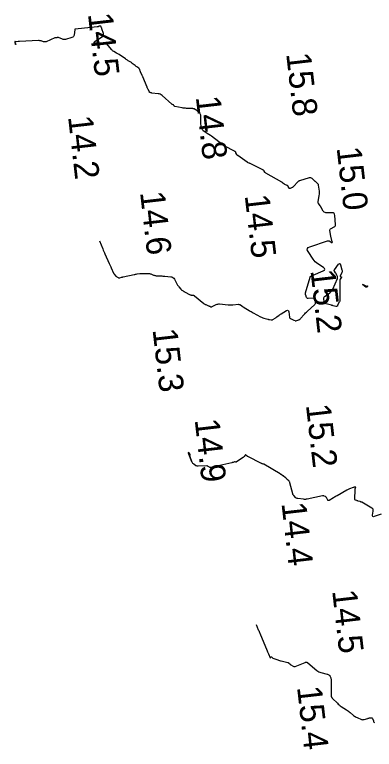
# Model space of a CAD drawing. Extents: x 1023796 to 1112670, y 656573 to 837340.
# Drawn here: x 1109917.5 to 1109990.4, y 680511.1 to 680660 of the extents above; entities that cross this region are included whole.
import ezdxf

# ---------------------------------------------------------------- set-up
doc = ezdxf.new("R2010")
doc.units = 0
doc.layers.add('V-CHAN-CONT-15FT', color=7, linetype='Continuous')
doc.layers.add('V-TOPO-SOUN', color=7, linetype='Continuous')

msp = doc.modelspace()

# ---------------------------------------------------------------- linework, layer by layer
at = {"layer": 'V-CHAN-CONT-15FT'}
for points in [[(1109934.65, 680614.2), (1109935.33, 680612.59), (1109935.44, 680612.32), (1109935.55, 680612.05), (1109935.67, 680611.78), (1109935.79, 680611.52), (1109936.66, 680609.56), (1109936.76, 680609.35), (1109936.85, 680609.15), (1109936.95, 680608.94), (1109937.04, 680608.73), (1109937.54, 680607.63), (1109937.58, 680607.56), (1109937.62, 680607.49), (1109937.67, 680607.42), (1109937.72, 680607.36), (1109937.93, 680607.1), (1109937.99, 680607.04), (1109938.05, 680606.99), (1109938.12, 680606.94), (1109938.19, 680606.9), (1109938.49, 680606.74), (1109938.56, 680606.7), (1109938.64, 680606.69), (1109938.72, 680606.69), (1109938.8, 680606.7), (1109939.15, 680606.8), (1109939.24, 680606.83), (1109939.32, 680606.85), (1109939.41, 680606.87), (1109939.5, 680606.89), (1109941.7, 680607.36), (1109941.85, 680607.39), (1109941.99, 680607.42), (1109942.14, 680607.45), (1109942.29, 680607.47), (1109942.88, 680607.55), (1109943.03, 680607.56), (1109943.18, 680607.58), (1109943.33, 680607.58), (1109943.48, 680607.58), (1109944.52, 680607.57), (1109944.66, 680607.56), (1109944.8, 680607.54), (1109944.94, 680607.5), (1109945.08, 680607.46), (1109945.62, 680607.24), (1109945.75, 680607.2), (1109945.89, 680607.16), (1109946.03, 680607.14), (1109946.18, 680607.12), (1109947.09, 680607.07), (1109947.29, 680607.06), (1109947.49, 680607.05), (1109947.69, 680607.03), (1109947.89, 680607.01), (1109949.11, 680606.91), (1109949.35, 680606.86), (1109949.55, 680606.77), (1109949.72, 680606.62), (1109949.85, 680606.42), (1109950.44, 680605.34), (1109950.51, 680605.22), (1109950.58, 680605.1), (1109950.66, 680604.99), (1109950.74, 680604.88), (1109951.16, 680604.37), (1109951.21, 680604.31), (1109951.26, 680604.26), (1109951.32, 680604.21), (1109951.38, 680604.17), (1109951.64, 680604.02), (1109951.71, 680603.98), (1109951.77, 680603.94), (1109951.84, 680603.91), (1109951.9, 680603.87), (1109953.06, 680603.27), (1109953.13, 680603.24), (1109953.2, 680603.22), (1109953.27, 680603.2), (1109953.34, 680603.19), (1109953.63, 680603.17), (1109953.71, 680603.15), (1109953.77, 680603.13), (1109953.84, 680603.1), (1109953.9, 680603.06), (1109955.8, 680601.51), (1109955.9, 680601.44), (1109956, 680601.37), (1109956.1, 680601.31), (1109956.21, 680601.25), (1109956.76, 680601.01), (1109956.82, 680600.98), (1109956.88, 680600.96), (1109956.94, 680600.93), (1109957, 680600.91), (1109957.25, 680600.83), (1109957.31, 680600.82), (1109957.38, 680600.82), (1109957.44, 680600.83), (1109957.49, 680600.85), (1109958.34, 680601.25), (1109958.51, 680601.32), (1109958.67, 680601.36), (1109958.85, 680601.38), (1109959.02, 680601.38), (1109960.77, 680601.24), (1109960.99, 680601.23), (1109961.22, 680601.22), (1109961.44, 680601.22), (1109961.67, 680601.24), (1109962.86, 680601.32), (1109962.94, 680601.31), (1109963.01, 680601.3), (1109963.08, 680601.28), (1109963.14, 680601.25), (1109963.43, 680601.06), (1109963.47, 680601.03), (1109963.52, 680601), (1109963.57, 680600.97), (1109963.61, 680600.94), (1109963.8, 680600.8), (1109963.84, 680600.77), (1109963.89, 680600.74), (1109963.94, 680600.71), (1109963.98, 680600.68), (1109965.03, 680600.05), (1109965.22, 680599.94), (1109965.41, 680599.83), (1109965.6, 680599.72), (1109965.79, 680599.61), (1109967.32, 680598.78), (1109967.48, 680598.71), (1109967.63, 680598.64), (1109967.79, 680598.58), (1109967.95, 680598.53), (1109968.76, 680598.31), (1109968.85, 680598.29), (1109968.94, 680598.27), (1109969.03, 680598.25), (1109969.12, 680598.23), (1109969.48, 680598.15), (1109969.57, 680598.14), (1109969.66, 680598.15), (1109969.74, 680598.17), (1109969.82, 680598.22), (1109970.25, 680598.51), (1109970.35, 680598.57), (1109970.45, 680598.64), (1109970.54, 680598.71), (1109970.63, 680598.78), (1109971.06, 680599.12), (1109971.16, 680599.2), (1109971.27, 680599.28), (1109971.38, 680599.35), (1109971.49, 680599.41), (1109972.57, 680600.03), (1109972.74, 680600.1), (1109972.87, 680600.08), (1109972.96, 680599.99), (1109973.01, 680599.81), (1109973.16, 680598.74), (1109973.19, 680598.63), (1109973.23, 680598.54), (1109973.31, 680598.47), (1109973.4, 680598.42), (1109973.94, 680598.17), (1109974.07, 680598.11), (1109974.29, 680598.01), (1109974.34, 680597.99), (1109974.38, 680597.98), (1109974.43, 680597.98), (1109974.47, 680597.99), (1109975.04, 680598.17), (1109975.14, 680598.21), (1109975.24, 680598.26), (1109975.33, 680598.33), (1109975.41, 680598.41), (1109976.13, 680599.24), (1109976.28, 680599.41), (1109976.43, 680599.57), (1109976.59, 680599.72), (1109976.75, 680599.88), (1109978.28, 680601.31), (1109978.36, 680601.4), (1109978.41, 680601.51), (1109978.44, 680601.62), (1109978.44, 680601.75), (1109978.38, 680602.27), (1109978.36, 680602.39), (1109978.3, 680602.47), (1109978.21, 680602.51), (1109978.09, 680602.53), (1109976.97, 680602.5), (1109976.85, 680602.51), (1109976.76, 680602.55), (1109976.69, 680602.62), (1109976.63, 680602.71), (1109976.45, 680603.16), (1109976.41, 680603.27), (1109976.39, 680603.38), (1109976.4, 680603.5), (1109976.42, 680603.61), (1109977.33, 680606.83), (1109977.36, 680606.88), (1109977.39, 680606.93), (1109977.43, 680606.97), (1109977.48, 680607), (1109977.71, 680607.1), (1109977.77, 680607.13), (1109977.83, 680607.15), (1109977.88, 680607.18), (1109977.94, 680607.2), (1109979.99, 680608.11), (1109980.23, 680608.25), (1109980.31, 680608.41), (1109980.25, 680608.58), (1109980.04, 680608.75), (1109978.89, 680609.49), (1109978.61, 680609.69), (1109978.36, 680609.92), (1109978.14, 680610.17), (1109977.94, 680610.44), (1109976.93, 680612.02), (1109976.78, 680612.35), (1109976.79, 680612.63), (1109976.96, 680612.84), (1109977.28, 680613), (1109980.9, 680614.17), (1109981, 680614.19), (1109981.11, 680614.19), (1109981.21, 680614.17), (1109981.31, 680614.12), (1109981.71, 680613.87), (1109981.79, 680613.83), (1109981.84, 680613.83), (1109981.86, 680613.88), (1109981.84, 680613.97), (1109981.65, 680614.59), (1109981.61, 680614.73), (1109981.58, 680614.87), (1109981.55, 680615.01), (1109981.53, 680615.15), (1109981.36, 680616.25), (1109981.35, 680616.4), (1109981.39, 680616.53), (1109981.48, 680616.63), (1109981.6, 680616.71), (1109982.2, 680616.99), (1109982.33, 680617.07), (1109982.42, 680617.18), (1109982.47, 680617.31), (1109982.48, 680617.46), (1109982.37, 680619.35), (1109982.32, 680619.58), (1109982.21, 680619.75), (1109982.04, 680619.85), (1109981.8, 680619.89), (1109980.53, 680619.89), (1109980.37, 680619.91), (1109980.22, 680619.96), (1109980.1, 680620.06), (1109980.01, 680620.19), (1109979.6, 680620.92), (1109979.55, 680621.02), (1109979.49, 680621.11), (1109979.42, 680621.2), (1109979.36, 680621.29), (1109979.09, 680621.65), (1109979.03, 680621.75), (1109979, 680621.84), (1109978.98, 680621.95), (1109978.99, 680622.06), (1109979.21, 680623.38), (1109979.23, 680623.61), (1109979.25, 680623.83), (1109979.24, 680624.06), (1109979.22, 680624.28), (1109979.08, 680625.46), (1109979.07, 680625.54), (1109979.03, 680625.62), (1109978.99, 680625.69), (1109978.93, 680625.76), (1109978.66, 680626), (1109978.59, 680626.06), (1109978.52, 680626.12), (1109978.46, 680626.18), (1109978.39, 680626.24), (1109977.77, 680626.82), (1109977.64, 680626.91), (1109977.5, 680626.97), (1109977.35, 680626.98), (1109977.19, 680626.96), (1109975.17, 680626.37), (1109975.14, 680626.36), (1109975.11, 680626.35), (1109975.08, 680626.33), (1109975.05, 680626.31), (1109974.96, 680626.23), (1109974.93, 680626.21), (1109974.91, 680626.18), (1109974.88, 680626.16), (1109974.86, 680626.14), (1109974, 680625.19), (1109973.93, 680625.12), (1109973.86, 680625.06), (1109973.78, 680625.01), (1109973.69, 680624.97), (1109973.34, 680624.8), (1109973.26, 680624.78), (1109973.2, 680624.79), (1109973.14, 680624.82), (1109973.09, 680624.89), (1109972.93, 680625.2), (1109972.89, 680625.27), (1109972.83, 680625.34), (1109972.76, 680625.39), (1109972.69, 680625.43), (1109972.23, 680625.62), (1109972.18, 680625.64), (1109972.12, 680625.67), (1109972.07, 680625.71), (1109972.03, 680625.74), (1109971.85, 680625.9), (1109971.8, 680625.94), (1109971.75, 680625.98), (1109971.7, 680626.01), (1109971.65, 680626.04), (1109968.36, 680627.91), (1109968.31, 680627.94), (1109968.26, 680627.98), (1109968.22, 680628.03), (1109968.18, 680628.08), (1109968.06, 680628.31), (1109968.02, 680628.36), (1109967.98, 680628.41), (1109967.93, 680628.45), (1109967.88, 680628.48), (1109965.18, 680629.86), (1109965.13, 680629.88), (1109965.09, 680629.9), (1109965.04, 680629.92), (1109964.99, 680629.94), (1109964.79, 680630.01), (1109964.74, 680630.03), (1109964.7, 680630.06), (1109964.65, 680630.08), (1109964.61, 680630.11), (1109962.68, 680631.47), (1109962.62, 680631.51), (1109962.57, 680631.57), (1109962.53, 680631.62), (1109962.5, 680631.69), (1109962.33, 680632.04), (1109962.32, 680632.07), (1109962.31, 680632.09), (1109962.29, 680632.11), (1109962.28, 680632.13), (1109962.22, 680632.21), (1109962.2, 680632.23), (1109962.18, 680632.24), (1109962.17, 680632.26), (1109962.14, 680632.27), (1109959.95, 680633.47), (1109959.93, 680633.48), (1109959.91, 680633.49), (1109959.89, 680633.5), (1109959.87, 680633.51), (1109959.79, 680633.55), (1109959.77, 680633.56), (1109959.76, 680633.57), (1109959.74, 680633.58), (1109959.72, 680633.6), (1109957.39, 680635.39), (1109957.31, 680635.45), (1109957.23, 680635.5), (1109957.15, 680635.55), (1109957.06, 680635.6), (1109956.73, 680635.8), (1109956.65, 680635.85), (1109956.56, 680635.9), (1109956.48, 680635.96), (1109956.4, 680636.01), (1109955.71, 680636.51), (1109955.58, 680636.62), (1109955.48, 680636.75), (1109955.41, 680636.9), (1109955.37, 680637.06), (1109955.23, 680637.92), (1109955.2, 680638.11), (1109955.19, 680638.3), (1109955.18, 680638.49), (1109955.18, 680638.68), (1109955.22, 680639.5), (1109955.21, 680639.65), (1109955.17, 680639.79), (1109955.1, 680639.91), (1109955, 680640.03), (1109954.45, 680640.55), (1109954.38, 680640.6), (1109954.31, 680640.66), (1109954.24, 680640.71), (1109954.16, 680640.75), (1109953.84, 680640.91), (1109953.76, 680640.95), (1109953.67, 680640.97), (1109953.59, 680640.99), (1109953.5, 680641), (1109952.32, 680641.03), (1109952.09, 680641.04), (1109951.87, 680641.06), (1109951.64, 680641.09), (1109951.42, 680641.13), (1109949.91, 680641.44), (1109949.88, 680641.45), (1109949.86, 680641.47), (1109949.83, 680641.49), (1109949.82, 680641.52), (1109949.76, 680641.64), (1109949.74, 680641.67), (1109949.72, 680641.69), (1109949.69, 680641.71), (1109949.66, 680641.73), (1109949.47, 680641.79), (1109949.42, 680641.8), (1109949.38, 680641.82), (1109949.35, 680641.85), (1109949.31, 680641.87), (1109947.37, 680643.64), (1109947.19, 680643.78), (1109947, 680643.89), (1109946.79, 680643.96), (1109946.57, 680644), (1109945.27, 680644.14), (1109945.23, 680644.15), (1109945.18, 680644.16), (1109945.14, 680644.17), (1109945.09, 680644.18), (1109944.92, 680644.24), (1109944.88, 680644.26), (1109944.84, 680644.28), (1109944.82, 680644.31), (1109944.79, 680644.35), (1109944.51, 680644.89), (1109944.46, 680645), (1109944.41, 680645.1), (1109944.36, 680645.21), (1109944.32, 680645.32), (1109943.48, 680647.39), (1109943.43, 680647.49), (1109943.39, 680647.59), (1109943.34, 680647.69), (1109943.29, 680647.79), (1109943.07, 680648.23), (1109943.03, 680648.31), (1109943, 680648.39), (1109942.97, 680648.48), (1109942.94, 680648.56), (1109942.82, 680648.9), (1109942.79, 680648.98), (1109942.74, 680649.05), (1109942.69, 680649.11), (1109942.62, 680649.17), (1109942.23, 680649.43), (1109942.14, 680649.49), (1109942.05, 680649.55), (1109941.97, 680649.62), (1109941.89, 680649.69), (1109941.52, 680650.02), (1109941.43, 680650.09), (1109941.33, 680650.16), (1109941.24, 680650.23), (1109941.14, 680650.3), (1109940.51, 680650.7), (1109940.37, 680650.79), (1109940.23, 680650.88), (1109940.09, 680650.97), (1109939.95, 680651.06), (1109938.64, 680651.92), (1109938.51, 680652), (1109938.37, 680652.08), (1109938.24, 680652.16), (1109938.11, 680652.24), (1109937.58, 680652.55), (1109937.45, 680652.63), (1109937.33, 680652.72), (1109937.22, 680652.83), (1109937.12, 680652.94), (1109936.16, 680654.14), (1109936.14, 680654.16), (1109936.12, 680654.18), (1109936.1, 680654.2), (1109936.08, 680654.22), (1109935.99, 680654.29), (1109935.97, 680654.31), (1109935.94, 680654.32), (1109935.91, 680654.32), (1109935.89, 680654.33), (1109933.89, 680654.26), (1109933.63, 680654.27), (1109933.52, 680654.34), (1109933.57, 680654.45), (1109933.78, 680654.62), (1109935.28, 680655.62), (1109935.4, 680655.73), (1109935.48, 680655.86), (1109935.5, 680656.01), (1109935.47, 680656.18), (1109935.17, 680657.12), (1109935.16, 680657.18), (1109935.14, 680657.23), (1109935.12, 680657.28), (1109935.1, 680657.33), (1109935.02, 680657.57), (1109935, 680657.6), (1109934.98, 680657.63), (1109934.95, 680657.65), (1109934.92, 680657.67), (1109934.78, 680657.71), (1109934.74, 680657.72), (1109934.71, 680657.72), (1109934.67, 680657.71), (1109934.64, 680657.7), (1109934.41, 680657.59), (1109934.35, 680657.56), (1109934.3, 680657.55), (1109934.25, 680657.53), (1109934.19, 680657.53), (1109929.77, 680657.1), (1109929.76, 680657.1), (1109929.75, 680657.1), (1109929.75, 680657.1), (1109929.74, 680657.09), (1109929.72, 680657.07), (1109929.71, 680657.06), (1109929.71, 680657.05), (1109929.7, 680657.04), (1109929.7, 680657.04), (1109929.52, 680655.9), (1109929.47, 680655.72), (1109929.38, 680655.58), (1109929.25, 680655.47), (1109929.09, 680655.4), (1109927.77, 680654.99), (1109927.62, 680654.96), (1109927.47, 680654.96), (1109927.33, 680654.98), (1109927.19, 680655.03), (1109926.39, 680655.39), (1109926.36, 680655.4), (1109926.33, 680655.41), (1109926.31, 680655.41), (1109926.28, 680655.4), (1109926.17, 680655.38), (1109926.14, 680655.37), (1109926.11, 680655.37), (1109926.08, 680655.36), (1109926.05, 680655.36), (1109925.81, 680655.36), (1109925.76, 680655.36), (1109925.72, 680655.35), (1109925.67, 680655.34), (1109925.62, 680655.32), (1109923.87, 680654.55), (1109923.75, 680654.51), (1109923.62, 680654.49), (1109923.49, 680654.5), (1109923.36, 680654.52), (1109922.83, 680654.69), (1109922.7, 680654.73), (1109922.57, 680654.75), (1109922.43, 680654.76), (1109922.3, 680654.76), (1109918.46, 680654.61), (1109918.39, 680654.6), (1109918.32, 680654.6), (1109918.25, 680654.59), (1109918.17, 680654.59), (1109917.79, 680654.54), (1109917.77, 680654.54), (1109917.75, 680654.54), (1109917.72, 680654.55), (1109917.7, 680654.55), (1109917.6, 680654.57), (1109917.59, 680654.57), (1109917.57, 680654.57), (1109917.56, 680654.57), (1109917.55, 680654.56), (1109917.51, 680654.51), (1109917.5, 680654.49), (1109917.5, 680654.48), (1109917.5, 680654.47), (1109917.5, 680654.45), (1109917.71, 680653.99), (1109917.72, 680653.96), (1109917.72, 680653.95), (1109917.72, 680653.96), (1109917.7, 680653.98), (1109917.57, 680654.21)], [(1109991.73, 680558.75), (1109990.32, 680558.3), (1109990.16, 680558.27), (1109990.04, 680558.3), (1109989.99, 680558.41), (1109990, 680558.58), (1109990.14, 680559.4), (1109990.15, 680559.59), (1109990.11, 680559.76), (1109990.01, 680559.9), (1109989.85, 680560.02), (1109987.8, 680561.18), (1109987.72, 680561.22), (1109987.63, 680561.26), (1109987.55, 680561.3), (1109987.46, 680561.32), (1109987.06, 680561.44), (1109986.99, 680561.46), (1109986.93, 680561.48), (1109986.87, 680561.5), (1109986.81, 680561.52), (1109986.56, 680561.6), (1109986.5, 680561.63), (1109986.46, 680561.67), (1109986.44, 680561.72), (1109986.43, 680561.78), (1109986.48, 680563.85), (1109986.48, 680563.9), (1109986.49, 680563.94), (1109986.5, 680563.98), (1109986.51, 680564.03), (1109986.58, 680564.22), (1109986.59, 680564.25), (1109986.58, 680564.26), (1109986.57, 680564.27), (1109986.54, 680564.27), (1109986.42, 680564.25), (1109986.39, 680564.24), (1109986.36, 680564.24), (1109986.33, 680564.23), (1109986.3, 680564.23), (1109986.16, 680564.21), (1109986.13, 680564.21), (1109986.1, 680564.2), (1109986.07, 680564.19), (1109986.04, 680564.18), (1109985.31, 680563.9), (1109985.18, 680563.85), (1109985.05, 680563.79), (1109984.92, 680563.73), (1109984.8, 680563.66), (1109982.8, 680562.52), (1109982.62, 680562.42), (1109982.44, 680562.32), (1109982.26, 680562.21), (1109982.08, 680562.1), (1109981.21, 680561.57), (1109981.11, 680561.53), (1109981.03, 680561.53), (1109980.96, 680561.57), (1109980.91, 680561.65), (1109980.66, 680562.13), (1109980.62, 680562.19), (1109980.58, 680562.24), (1109980.52, 680562.29), (1109980.45, 680562.33), (1109980.17, 680562.45), (1109980.1, 680562.48), (1109980.03, 680562.49), (1109979.95, 680562.49), (1109979.88, 680562.48), (1109976.77, 680561.83), (1109976.57, 680561.79), (1109976.38, 680561.78), (1109976.18, 680561.78), (1109975.98, 680561.79), (1109974.87, 680561.93), (1109974.83, 680561.94), (1109974.78, 680561.95), (1109974.74, 680561.96), (1109974.7, 680561.98), (1109974.54, 680562.05), (1109974.5, 680562.07), (1109974.47, 680562.1), (1109974.43, 680562.13), (1109974.4, 680562.16), (1109974.04, 680562.54), (1109973.98, 680562.62), (1109973.92, 680562.71), (1109973.88, 680562.8), (1109973.85, 680562.89), (1109973.25, 680565.15), (1109973.21, 680565.25), (1109973.16, 680565.35), (1109973.1, 680565.44), (1109973.03, 680565.52), (1109972.72, 680565.83), (1109972.64, 680565.9), (1109972.55, 680565.98), (1109972.47, 680566.05), (1109972.38, 680566.12), (1109971.86, 680566.52), (1109971.81, 680566.56), (1109971.77, 680566.59), (1109971.72, 680566.63), (1109971.67, 680566.66), (1109971.47, 680566.8), (1109971.42, 680566.83), (1109971.37, 680566.87), (1109971.32, 680566.9), (1109971.27, 680566.93), (1109967.94, 680568.9), (1109967.92, 680568.91), (1109967.9, 680568.92), (1109967.87, 680568.93), (1109967.84, 680568.93), (1109967.73, 680568.95), (1109967.71, 680568.96), (1109967.68, 680568.97), (1109967.66, 680568.97), (1109967.64, 680568.98), (1109967.54, 680569.03), (1109967.48, 680569.07), (1109964.74, 680570.45), (1109964.68, 680570.48), (1109964.62, 680570.51), (1109964.57, 680570.55), (1109964.52, 680570.59), (1109964.33, 680570.76), (1109964.28, 680570.79), (1109964.24, 680570.8), (1109964.2, 680570.78), (1109964.16, 680570.74), (1109964, 680570.48), (1109963.96, 680570.42), (1109963.91, 680570.37), (1109963.86, 680570.32), (1109963.8, 680570.28), (1109962.42, 680569.36), (1109962.39, 680569.34), (1109962.36, 680569.33), (1109962.33, 680569.33), (1109962.3, 680569.34), (1109962.17, 680569.4), (1109962.14, 680569.41), (1109962.1, 680569.41), (1109962.07, 680569.41), (1109962.04, 680569.4), (1109961.75, 680569.28), (1109961.69, 680569.26), (1109961.63, 680569.24), (1109961.57, 680569.22), (1109961.51, 680569.2), (1109957.26, 680568.23), (1109957.18, 680568.21), (1109957.11, 680568.22), (1109957.04, 680568.24), (1109956.97, 680568.28), (1109956.7, 680568.47), (1109956.63, 680568.51), (1109956.56, 680568.54), (1109956.49, 680568.55), (1109956.41, 680568.56), (1109954.69, 680568.48), (1109954.57, 680568.49), (1109954.44, 680568.51), (1109954.33, 680568.55), (1109954.22, 680568.61), (1109953.79, 680568.9), (1109953.69, 680568.98), (1109953.61, 680569.07), (1109953.54, 680569.17), (1109953.48, 680569.28), (1109953.05, 680570.43), (1109953.03, 680570.48), (1109953.02, 680570.54), (1109953.01, 680570.59), (1109953.01, 680570.65), (1109953.02, 680570.87), (1109953.02, 680570.92), (1109953.01, 680570.97), (1109952.98, 680571.01), (1109952.94, 680571.05), (1109952.66, 680571.28), (1109952.64, 680571.29), (1109952.63, 680571.29), (1109952.62, 680571.28), (1109952.63, 680571.26), (1109952.67, 680571.14), (1109952.67, 680571.11), (1109952.68, 680571.09), (1109952.69, 680571.06), (1109952.71, 680571.03), (1109953.29, 680569.48), (1109953.29, 680569.48), (1109953.29, 680569.48), (1109953.29, 680569.48), (1109953.31, 680569.4)], [(1109966.39, 680536.44), (1109966.85, 680535.35), (1109966.93, 680535.17), (1109967, 680534.99), (1109967.08, 680534.81), (1109967.16, 680534.63), (1109968.68, 680531.06), (1109968.74, 680530.91), (1109968.8, 680530.77), (1109968.86, 680530.62), (1109968.93, 680530.47), (1109969.27, 680529.67), (1109969.28, 680529.63), (1109969.3, 680529.62), (1109969.32, 680529.63), (1109969.34, 680529.66), (1109969.42, 680529.84), (1109969.44, 680529.87), (1109969.47, 680529.88), (1109969.49, 680529.88), (1109969.52, 680529.85), (1109969.66, 680529.7), (1109969.7, 680529.66), (1109969.73, 680529.63), (1109969.78, 680529.61), (1109969.82, 680529.59), (1109970.79, 680529.23), (1109970.97, 680529.17), (1109971.14, 680529.11), (1109971.33, 680529.06), (1109971.51, 680529.02), (1109972.86, 680528.72), (1109972.92, 680528.7), (1109972.97, 680528.68), (1109973.02, 680528.64), (1109973.06, 680528.6), (1109973.23, 680528.42), (1109973.28, 680528.37), (1109973.32, 680528.33), (1109973.37, 680528.29), (1109973.43, 680528.26), (1109973.93, 680527.95), (1109974.03, 680527.9), (1109974.13, 680527.88), (1109974.24, 680527.89), (1109974.35, 680527.92), (1109976.36, 680528.73), (1109976.4, 680528.75), (1109976.45, 680528.76), (1109976.49, 680528.76), (1109976.54, 680528.76), (1109976.73, 680528.75), (1109976.77, 680528.74), (1109976.81, 680528.73), (1109976.85, 680528.71), (1109976.89, 680528.68), (1109978.73, 680527.07), (1109978.91, 680526.93), (1109979.09, 680526.82), (1109979.29, 680526.73), (1109979.5, 680526.66), (1109980.78, 680526.33), (1109980.79, 680526.33), (1109980.8, 680526.33), (1109980.81, 680526.33), (1109980.82, 680526.34), (1109980.85, 680526.37), (1109980.86, 680526.38), (1109980.87, 680526.38), (1109980.88, 680526.38), (1109980.89, 680526.37), (1109981.13, 680526.2), (1109981.16, 680526.19), (1109981.18, 680526.18), (1109981.2, 680526.16), (1109981.22, 680526.15), (1109981.31, 680526.11), (1109981.33, 680526.09), (1109981.35, 680526.08), (1109981.36, 680526.06), (1109981.37, 680526.04), (1109981.53, 680525.61), (1109981.55, 680525.53), (1109981.57, 680525.45), (1109981.58, 680525.37), (1109981.59, 680525.29), (1109981.63, 680523.02), (1109981.64, 680522.9), (1109981.64, 680522.78), (1109981.63, 680522.66), (1109981.63, 680522.54), (1109981.6, 680521.88), (1109981.6, 680521.85), (1109981.6, 680521.82), (1109981.62, 680521.8), (1109981.63, 680521.77), (1109981.72, 680521.66), (1109981.73, 680521.64), (1109981.74, 680521.63), (1109981.76, 680521.61), (1109981.77, 680521.59), (1109981.81, 680521.51), (1109981.82, 680521.49), (1109981.83, 680521.48), (1109981.84, 680521.46), (1109981.86, 680521.44), (1109982.88, 680520.44), (1109983.06, 680520.27), (1109983.25, 680520.11), (1109983.45, 680519.96), (1109983.65, 680519.82), (1109984.75, 680519.1), (1109984.93, 680518.98), (1109985.11, 680518.85), (1109985.29, 680518.71), (1109985.46, 680518.57), (1109986.14, 680517.98), (1109986.31, 680517.85), (1109986.48, 680517.74), (1109986.66, 680517.63), (1109986.85, 680517.55), (1109987.73, 680517.19), (1109987.87, 680517.14), (1109988.01, 680517.12), (1109988.16, 680517.13), (1109988.31, 680517.16), (1109989.01, 680517.38), (1109989.09, 680517.41), (1109989.18, 680517.43), (1109989.27, 680517.45), (1109989.37, 680517.47), (1109989.73, 680517.53), (1109989.82, 680517.53), (1109989.89, 680517.51), (1109989.94, 680517.46), (1109989.98, 680517.39), (1109990.18, 680516.87), (1109990.22, 680516.75), (1109990.29, 680516.65), (1109990.36, 680516.56)]]:
    msp.add_lwpolyline(points, dxfattribs=at)
for points in [[(1109983.84, 680608.05), (1109983.82, 680607.91), (1109983.77, 680607.77), (1109983.44, 680607.05), (1109983.43, 680607.01), (1109983.44, 680606.98), (1109983.46, 680606.96), (1109983.49, 680606.95), (1109983.65, 680606.9), (1109983.68, 680606.88), (1109983.69, 680606.86), (1109983.69, 680606.84), (1109983.68, 680606.81), (1109983.45, 680606.44), (1109983.41, 680606.37), (1109983.38, 680606.29), (1109983.36, 680606.21), (1109983.35, 680606.13), (1109983.38, 680602.2), (1109983.37, 680602.08), (1109983.35, 680601.96), (1109983.31, 680601.84), (1109983.26, 680601.73), (1109982.92, 680601.11), (1109982.91, 680601.1), (1109982.9, 680601.08), (1109982.9, 680601.06), (1109982.89, 680601.05), (1109982.88, 680600.99), (1109982.87, 680600.97), (1109982.86, 680600.96), (1109982.85, 680600.95), (1109982.84, 680600.95), (1109982.67, 680600.9), (1109982.63, 680600.89), (1109982.6, 680600.89), (1109982.56, 680600.89), (1109982.53, 680600.89), (1109982.05, 680601.03), (1109981.96, 680601.05), (1109981.87, 680601.08), (1109981.78, 680601.1), (1109981.69, 680601.13), (1109980.57, 680601.44), (1109980.43, 680601.5), (1109980.33, 680601.59), (1109980.26, 680601.7), (1109980.22, 680601.85), (1109980.15, 680602.49), (1109980.15, 680602.64), (1109980.19, 680602.78), (1109980.27, 680602.89), (1109980.38, 680602.99), (1109981.32, 680603.65), (1109981.51, 680603.8), (1109981.68, 680603.97), (1109981.81, 680604.17), (1109981.92, 680604.38), (1109982.89, 680606.56), (1109982.92, 680606.66), (1109982.93, 680606.75), (1109982.92, 680606.85), (1109982.89, 680606.95), (1109982.71, 680607.36), (1109982.66, 680607.45), (1109982.62, 680607.53), (1109982.56, 680607.62), (1109982.51, 680607.7), (1109982.27, 680608.01), (1109982.23, 680608.09), (1109982.21, 680608.17), (1109982.23, 680608.25), (1109982.27, 680608.33), (1109983.08, 680609.42), (1109983.21, 680609.55), (1109983.32, 680609.58), (1109983.41, 680609.52), (1109983.49, 680609.35), (1109983.8, 680608.32), (1109983.83, 680608.18)], [(1109988.79, 680604.99), (1109988.81, 680604.99), (1109988.82, 680604.99), (1109988.97, 680605.02), (1109989, 680605.03), (1109989.01, 680605.02), (1109989.01, 680605.01), (1109989, 680604.99), (1109988.89, 680604.82), (1109988.87, 680604.8), (1109988.85, 680604.78), (1109988.83, 680604.78), (1109988.81, 680604.77), (1109988.7, 680604.77), (1109988.68, 680604.77), (1109988.66, 680604.78), (1109988.63, 680604.79), (1109988.61, 680604.8), (1109988.06, 680605.29), (1109988, 680605.34), (1109987.99, 680605.37), (1109988.02, 680605.36), (1109988.09, 680605.33), (1109988.63, 680605.05), (1109988.64, 680605.04), (1109988.66, 680605.03), (1109988.68, 680605.03), (1109988.69, 680605.02), (1109988.76, 680605), (1109988.77, 680604.99)]]:
    msp.add_lwpolyline(points, close=True, dxfattribs=at)

# ---------------------------------------------------------------- texts
at = {"layer": 'V-TOPO-SOUN'}
for s, p in [('14.5 ', (1109932.33, 680660.18)), ('15.8 ', (1109972.49, 680652.1)), ('14.8 ', (1109954.18, 680643.34)), ('14.2 ', (1109928.3, 680639.34)), ('15.0 ', (1109982.71, 680633.04)), ('14.6 ', (1109942.89, 680624.01)), ('14.5 ', (1109964.09, 680623.37)), ('15.2 ', (1109977.41, 680608.17)), ('15.3 ', (1109945.42, 680596.2)), ('15.2 ', (1109976.49, 680580.91)), ('14.9 ', (1109953.95, 680577.92)), ('14.4 ', (1109971.54, 680560.99)), ('14.5 ', (1109981.81, 680543.25)), ('15.4 ', (1109974.69, 680523.72))]:
    msp.add_text(s, height=5, rotation=276.5594, dxfattribs=at).set_placement(p)

doc.saveas('drawing.dxf')
